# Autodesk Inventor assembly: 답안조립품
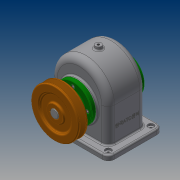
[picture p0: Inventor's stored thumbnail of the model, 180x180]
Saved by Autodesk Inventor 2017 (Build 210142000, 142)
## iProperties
Part Number: 답안조립품
Material: 일반
Document SubType Name: Assembly
Designer: 20
Author: 20
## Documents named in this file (14)
- C:\Users\20\Desktop\480310V1011\답안조립품.iam
- C:\Users\20\Desktop\480310V1011\본체.ipt
- C:\Users\20\Desktop\480310V1011\앞커버.ipt
- C:\Users\20\Desktop\480310V1011\뒤커버.ipt
- C:\Users\20\Desktop\480310V1011\베어링 6203.ipt
- C:\Users\20\Desktop\480310V1011\축.ipt
- C:\Users\20\Desktop\480310V1011\스퍼기어.ipt
- C:\Users\20\Desktop\480310V1011\키 6x6x22.ipt
- C:\Users\20\Desktop\480310V1011\부시.ipt
- C:\Users\20\Desktop\480310V1011\오일 실 28 40 8.ipt
- C:\Users\20\Desktop\480310V1011\V-벨트풀리.ipt
- C:\Users\20\Desktop\480310V1011\키 5x5x18.ipt
- C:\Users\20\Desktop\480310V1011\멈춤나사 M4.ipt
- C:\Users\20\Desktop\480310V1011\볼트 M4.ipt
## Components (1 placed, 1 different names)
1. V-벨트풀리:1 — 플러쉬:2
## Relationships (1: Flush 1)
- 플러쉬:2 [Flush]: V-벨트풀리:1
